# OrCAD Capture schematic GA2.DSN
size A
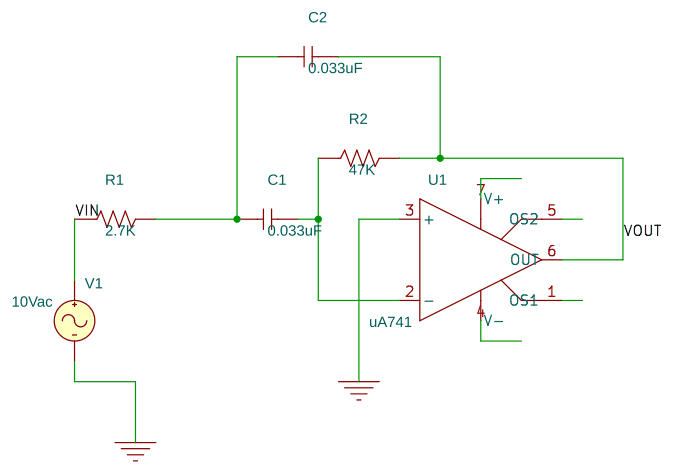
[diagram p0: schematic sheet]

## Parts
C1  0.033uF  [RAD/CK05]
C2  0.033uF  [RAD/CK05]
R1  2.7K  [AX/RC05]
R2  47K  [AX/RC05]
U1  uA741  [DIP.100/8/W.300/L.450]
V1  VAC

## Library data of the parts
C1 C2 = C
R1 R2 = R
U1 = uA741
V1 = VAC: ACMAG: 10Vac

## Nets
VIN: R1.1 V1.1(+)
0: U1.3(+) V1.2(-)
VOUT: C2.2 R2.2 U1.6(OUT)
N02077: C1.2 R2.1 U1.2(-)
N02126: C1.1 C2.1 R1.2

Not connected (* = marked no-connect by the designer): U1 1(OS1) 4(V-) 5(OS2) 7(V+)
